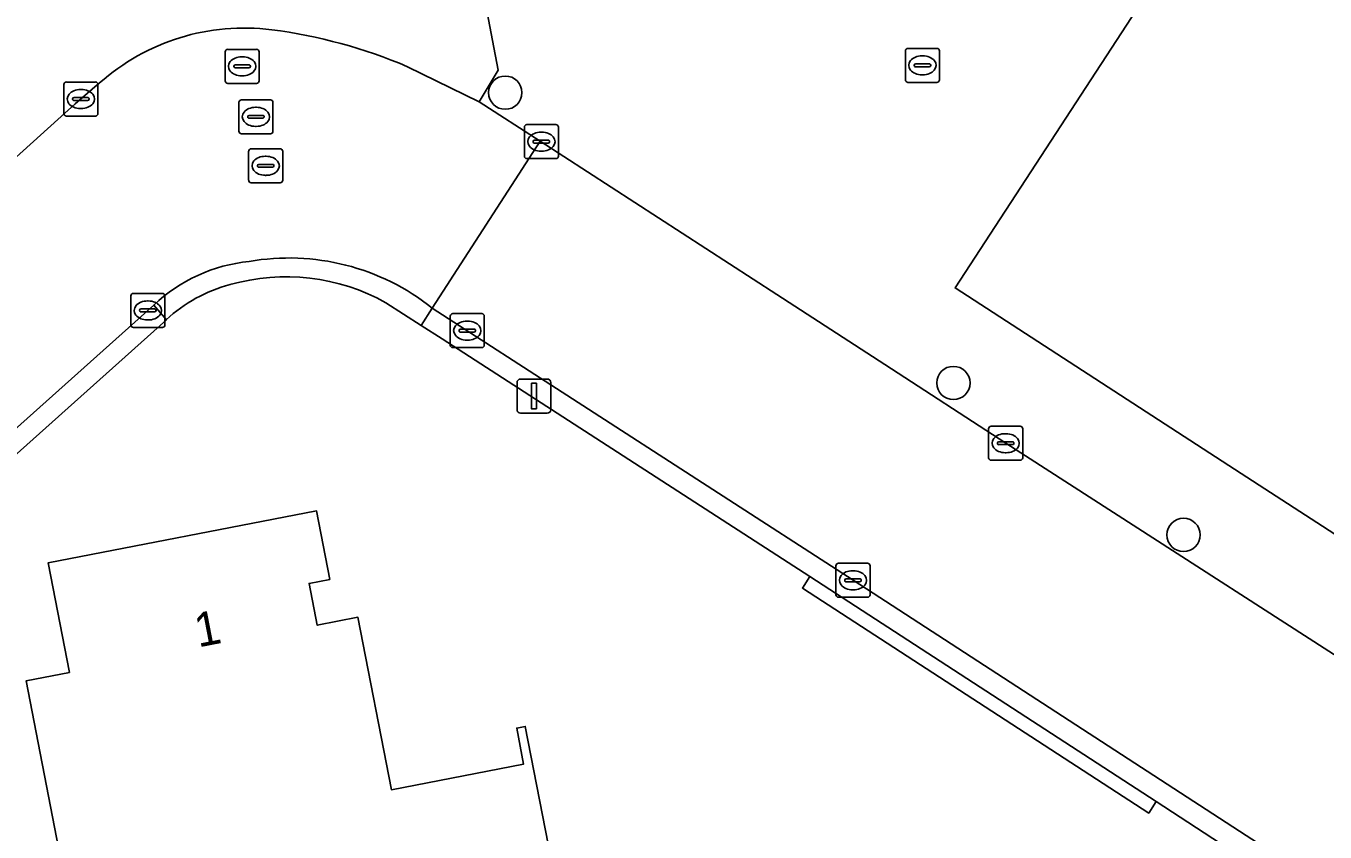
# Model space of a CAD drawing. Extents: x 157648 to 158502, y 379212 to 380938.
# Drawn here: x 158355.36 to 158393.55, y 380471.39 to 380495.07 of the extents above; entities that cross this region are included whole.
import ezdxf

# ---------------------------------------------------------------- set-up
doc = ezdxf.new("R2010")
doc.units = 0
for name, color, linetype in [('IMGEO_Boom', 7, 'Continuous'), ('IMGEO_Erf', 7, 'Continuous'), ('IMGEO_Groenvoorziening', 7, 'Continuous'), ('IMGEO_Haag', 7, 'Continuous'), ('IMGEO_Hek', 7, 'Continuous'), ('IMGEO_Kolk', 7, 'Continuous'), ('IMGEO_Lichtmast', 7, 'Continuous'), ('IMGEO_Pand', 7, 'Continuous'), ('IMGEO_Pand_nummerreeks', 7, 'Continuous'), ('IMGEO_Rijbaan_lokaal_open', 7, 'Continuous'), ('IMGEO_Rioolput', 7, 'Continuous'), ('IMGEO_Voetpad_open', 7, 'Continuous')]:
    doc.layers.add(name, color=color, linetype=linetype)

msp = doc.modelspace()

# ---------------------------------------------------------------- linework, layer by layer
at = {"layer": 'IMGEO_Boom'}
for centre in [(158369.454, 380493.113), (158382.628, 380484.583), (158389.393, 380480.119)]:
    msp.add_circle(centre, 0.489, dxfattribs=at)
at = {"layer": 'IMGEO_Erf'}
for points in [[(158380.582, 380515.062), (158381.881, 380508.316), (158377.849, 380507.539), (158377.739, 380508.108), (158374.457, 380507.476), (158370.48, 380506.71), (158371.129, 380503.345), (158363.628, 380501.901), (158364.015, 380500.041), (158364.616, 380497.15), (158368.462, 380497.886), (158387.396, 380501.51), (158388.452, 380496.229), (158382.675, 380487.376), (158391.091, 380481.923), (158399.153, 380476.703), (158402.85, 380476.983), (158408.306, 380485.065), (158411.427, 380489.696)], [(158393.178, 380468.812), (158392.666, 380469.161), (158390.971, 380470.261), (158391.189, 380470.597), (158388.589, 380472.285), (158388.371, 380471.949), (158378.189, 380478.557), (158378.407, 380478.893), (158367.597, 380485.882), (158366.984, 380486.274), (158365.946, 380486.942)], [(158359.49, 380486.443), (158322.721, 380453.552)]]:
    msp.add_lwpolyline(points, dxfattribs=at)
msp.add_lwpolyline([(158356.657, 380469.164), (158356.316, 380470.924), (158355.366, 380475.832), (158356.639, 380476.078), (158356.016, 380479.298), (158363.906, 380480.825), (158364.296, 380478.811), (158363.688, 380478.694), (158363.926, 380477.467), (158365.124, 380477.699), (158366.105, 380472.634), (158369.993, 380473.387), (158369.789, 380474.442), (158370.042, 380474.491), (158370.799, 380470.582), (158365.891, 380469.632), (158361.463, 380468.775), (158361.217, 380470.047)], close=True, dxfattribs=at)
for centre, radius, start, end in [((158363.014, 380481.675), 6.028, 60.8988, 105.9108), ((158362.461, 380483.255), 4.358, 104.6089, 132.9845)]:
    msp.add_arc(centre, radius, start, end, dxfattribs=at)
at = {"layer": 'IMGEO_Groenvoorziening'}
msp.add_lwpolyline([(158378.407, 380478.893), (158378.189, 380478.557), (158388.371, 380471.949), (158388.589, 380472.285)], close=True, dxfattribs=at)
at = {"layer": 'IMGEO_Haag'}
msp.add_lwpolyline([(158378.407, 380478.893), (158378.189, 380478.557), (158388.371, 380471.949), (158388.589, 380472.285)], close=True, dxfattribs=at)
at = {"layer": 'IMGEO_Hek'}
for points in [[(158391.091, 380481.923), (158382.675, 380487.376), (158388.452, 380496.229), (158387.396, 380501.51)], [(158378.407, 380478.893), (158367.597, 380485.882)], [(158388.589, 380472.285), (158391.189, 380470.597)]]:
    msp.add_lwpolyline(points, dxfattribs=at)
at = {"layer": 'IMGEO_Kolk'}
for p, q in [((158381.217, 380493.489), (158381.217, 380494.341)), ((158381.292, 380494.415), (158382.144, 380494.415)), ((158381.705, 380494.195), (158381.73, 380494.195)), ((158382.218, 380494.341), (158382.218, 380493.489)), ((158381.476, 380493.909), (158381.476, 380493.921)), ((158381.914, 380493.872), (158381.516, 380493.872)), ((158381.519, 380493.958), (158381.917, 380493.958)), ((158381.96, 380493.921), (158381.96, 380493.909)), ((158356.477, 380492.5), (158356.477, 380493.352)), ((158356.552, 380493.426), (158357.404, 380493.426)), ((158357.478, 380493.352), (158357.478, 380492.5)), ((158382.144, 380493.415), (158381.292, 380493.415)), ((158381.728, 380493.635), (158381.703, 380493.635)), ((158356.779, 380492.969), (158357.177, 380492.969)), ((158356.965, 380493.206), (158356.99, 380493.206)), ((158356.736, 380492.92), (158356.736, 380492.932)), ((158357.174, 380492.883), (158356.776, 380492.883)), ((158356.988, 380492.646), (158356.963, 380492.646)), ((158357.22, 380492.932), (158357.22, 380492.92)), ((158357.404, 380492.426), (158356.552, 380492.426)), ((158370.09, 380492.175), (158370.942, 380492.175)), ((158370.015, 380491.249), (158370.015, 380492.101)), ((158370.503, 380491.955), (158370.528, 380491.955)), ((158371.016, 380492.101), (158371.016, 380491.249)), ((158370.274, 380491.669), (158370.274, 380491.681)), ((158370.712, 380491.632), (158370.314, 380491.632)), ((158370.317, 380491.718), (158370.715, 380491.718)), ((158370.758, 380491.681), (158370.758, 380491.669)), ((158370.942, 380491.175), (158370.09, 380491.175)), ((158370.526, 380491.395), (158370.501, 380491.395)), ((158358.521, 380487.214), (158359.373, 380487.214)), ((158358.446, 380486.288), (158358.446, 380487.14)), ((158358.934, 380486.994), (158358.959, 380486.994)), ((158359.447, 380487.14), (158359.447, 380486.288)), ((158358.705, 380486.708), (158358.705, 380486.72)), ((158359.143, 380486.671), (158358.745, 380486.671)), ((158358.748, 380486.757), (158359.146, 380486.757)), ((158359.189, 380486.72), (158359.189, 380486.708)), ((158367.836, 380485.696), (158367.836, 380486.548)), ((158367.911, 380486.622), (158368.763, 380486.622)), ((158368.837, 380486.548), (158368.837, 380485.696)), ((158359.373, 380486.214), (158358.521, 380486.214)), ((158358.957, 380486.434), (158358.932, 380486.434)), ((158368.095, 380486.116), (158368.095, 380486.128)), ((158368.533, 380486.079), (158368.135, 380486.079)), ((158368.138, 380486.165), (158368.536, 380486.165)), ((158368.324, 380486.402), (158368.349, 380486.402)), ((158368.579, 380486.128), (158368.579, 380486.116)), ((158368.347, 380485.842), (158368.322, 380485.842)), ((158368.763, 380485.622), (158367.911, 380485.622)), ((158383.663, 380482.388), (158383.663, 380483.24)), ((158383.738, 380483.314), (158384.59, 380483.314)), ((158384.151, 380483.094), (158384.176, 380483.094)), ((158384.664, 380483.24), (158384.664, 380482.388)), ((158383.922, 380482.808), (158383.922, 380482.82)), ((158384.36, 380482.771), (158383.962, 380482.771)), ((158383.965, 380482.857), (158384.363, 380482.857)), ((158384.406, 380482.82), (158384.406, 380482.808)), ((158384.59, 380482.314), (158383.738, 380482.314)), ((158384.174, 380482.534), (158384.149, 380482.534)), ((158379.175, 380478.361), (158379.175, 380479.213)), ((158379.25, 380479.287), (158380.102, 380479.287)), ((158380.176, 380479.213), (158380.176, 380478.361)), ((158379.477, 380478.83), (158379.875, 380478.83)), ((158379.663, 380479.067), (158379.688, 380479.067)), ((158379.434, 380478.781), (158379.434, 380478.793)), ((158379.872, 380478.744), (158379.474, 380478.744)), ((158379.686, 380478.507), (158379.661, 380478.507)), ((158379.918, 380478.793), (158379.918, 380478.781)), ((158380.102, 380478.287), (158379.25, 380478.287))]:
    msp.add_line(p, q, dxfattribs=at)
for points in [[(158381.217, 380493.489), (158381.217, 380494.341)], [(158381.292, 380494.415), (158382.144, 380494.415)], [(158382.218, 380494.341), (158382.218, 380493.489)], [(158356.477, 380492.5), (158356.477, 380493.352)], [(158356.552, 380493.426), (158357.404, 380493.426)], [(158357.478, 380493.352), (158357.478, 380492.5)], [(158382.144, 380493.415), (158381.292, 380493.415)], [(158357.404, 380492.426), (158356.552, 380492.426)], [(158370.09, 380492.175), (158370.942, 380492.175)], [(158370.015, 380491.249), (158370.015, 380492.101)], [(158371.016, 380492.101), (158371.016, 380491.249)], [(158370.942, 380491.175), (158370.09, 380491.175)], [(158358.521, 380487.214), (158359.373, 380487.214)], [(158358.446, 380486.288), (158358.446, 380487.14)], [(158359.447, 380487.14), (158359.447, 380486.288)], [(158367.836, 380485.696), (158367.836, 380486.548)], [(158367.911, 380486.622), (158368.763, 380486.622)], [(158368.837, 380486.548), (158368.837, 380485.696)], [(158359.373, 380486.214), (158358.521, 380486.214)], [(158368.763, 380485.622), (158367.911, 380485.622)], [(158383.663, 380482.388), (158383.663, 380483.24)], [(158383.738, 380483.314), (158384.59, 380483.314)], [(158384.664, 380483.24), (158384.664, 380482.388)], [(158384.59, 380482.314), (158383.738, 380482.314)], [(158379.175, 380478.361), (158379.175, 380479.213)], [(158379.25, 380479.287), (158380.102, 380479.287)], [(158380.176, 380479.213), (158380.176, 380478.361)], [(158380.102, 380478.287), (158379.25, 380478.287)]]:
    msp.add_lwpolyline(points, dxfattribs=at)
for centre, radius, start, end in [((158381.294, 380494.339), 0.0765, 91.552, 178.448), ((158381.294, 380494.339), 0.0765, 91.552, 178.448), ((158382.142, 380494.339), 0.0765, 1.552, 88.448), ((158382.142, 380494.339), 0.0765, 1.552, 88.448), ((158381.516, 380493.918), 0.0403, 85.8775, 175.7526), ((158381.513, 380493.908), 0.0366, 178.938, 274.7102), ((158381.917, 380493.915), 0.043, 264.8664, 352.4533), ((158381.921, 380493.92), 0.0386, 1.7309, 96.639), ((158356.554, 380493.35), 0.0765, 91.552, 178.448), ((158356.554, 380493.35), 0.0765, 91.552, 178.448), ((158357.402, 380493.35), 0.0765, 1.552, 88.448), ((158357.402, 380493.35), 0.0765, 1.552, 88.448), ((158381.294, 380493.491), 0.0765, 181.552, 268.448), ((158381.294, 380493.491), 0.0765, 181.552, 268.448), ((158382.142, 380493.491), 0.0765, 271.552, 358.448), ((158382.142, 380493.491), 0.0765, 271.552, 358.448), ((158356.776, 380492.929), 0.0403, 85.8775, 175.7526), ((158357.181, 380492.931), 0.0386, 1.7309, 96.639), ((158356.773, 380492.919), 0.0366, 178.938, 274.7102), ((158357.177, 380492.926), 0.043, 264.8664, 352.4533), ((158356.554, 380492.502), 0.0765, 181.552, 268.448), ((158356.554, 380492.502), 0.0765, 181.552, 268.448), ((158357.402, 380492.502), 0.0765, 271.552, 358.448), ((158357.402, 380492.502), 0.0765, 271.552, 358.448), ((158370.092, 380492.099), 0.0765, 91.552, 178.448), ((158370.092, 380492.099), 0.0765, 91.552, 178.448), ((158370.94, 380492.099), 0.0765, 1.552, 88.448), ((158370.94, 380492.099), 0.0765, 1.552, 88.448), ((158370.314, 380491.678), 0.0403, 85.8775, 175.7526), ((158370.311, 380491.668), 0.0366, 178.938, 274.7102), ((158370.715, 380491.675), 0.043, 264.8664, 352.4533), ((158370.719, 380491.68), 0.0386, 1.7309, 96.639), ((158370.092, 380491.251), 0.0765, 181.552, 268.448), ((158370.092, 380491.251), 0.0765, 181.552, 268.448), ((158370.94, 380491.251), 0.0765, 271.552, 358.448), ((158370.94, 380491.251), 0.0765, 271.552, 358.448), ((158358.523, 380487.138), 0.0765, 91.552, 178.448), ((158358.523, 380487.138), 0.0765, 91.552, 178.448), ((158359.371, 380487.138), 0.0765, 1.552, 88.448), ((158359.371, 380487.138), 0.0765, 1.552, 88.448), ((158358.745, 380486.717), 0.0403, 85.8775, 175.7526), ((158358.742, 380486.707), 0.0366, 178.938, 274.7102), ((158359.146, 380486.714), 0.043, 264.8664, 352.4533), ((158359.15, 380486.719), 0.0386, 1.7309, 96.639), ((158367.913, 380486.546), 0.0765, 91.552, 178.448), ((158367.913, 380486.546), 0.0765, 91.552, 178.448), ((158368.761, 380486.546), 0.0765, 1.552, 88.448), ((158368.761, 380486.546), 0.0765, 1.552, 88.448), ((158358.523, 380486.29), 0.0765, 181.552, 268.448), ((158358.523, 380486.29), 0.0765, 181.552, 268.448), ((158359.371, 380486.29), 0.0765, 271.552, 358.448), ((158359.371, 380486.29), 0.0765, 271.552, 358.448), ((158368.135, 380486.125), 0.0403, 85.8775, 175.7526), ((158368.132, 380486.115), 0.0366, 178.938, 274.7102), ((158368.536, 380486.122), 0.043, 264.8664, 352.4533), ((158368.54, 380486.127), 0.0386, 1.7309, 96.639), ((158367.913, 380485.698), 0.0765, 181.552, 268.448), ((158367.913, 380485.698), 0.0765, 181.552, 268.448), ((158368.761, 380485.698), 0.0765, 271.552, 358.448), ((158368.761, 380485.698), 0.0765, 271.552, 358.448), ((158383.74, 380483.238), 0.0765, 91.552, 178.448), ((158383.74, 380483.238), 0.0765, 91.552, 178.448), ((158384.588, 380483.238), 0.0765, 1.552, 88.448), ((158384.588, 380483.238), 0.0765, 1.552, 88.448), ((158383.962, 380482.817), 0.0403, 85.8775, 175.7526), ((158383.959, 380482.807), 0.0366, 178.938, 274.7102), ((158384.363, 380482.814), 0.043, 264.8664, 352.4533), ((158384.367, 380482.819), 0.0386, 1.7309, 96.639), ((158383.74, 380482.39), 0.0765, 181.552, 268.448), ((158383.74, 380482.39), 0.0765, 181.552, 268.448), ((158384.588, 380482.39), 0.0765, 271.552, 358.448), ((158384.588, 380482.39), 0.0765, 271.552, 358.448), ((158379.252, 380479.211), 0.0765, 91.552, 178.448), ((158379.252, 380479.211), 0.0765, 91.552, 178.448), ((158380.1, 380479.211), 0.0765, 1.552, 88.448), ((158380.1, 380479.211), 0.0765, 1.552, 88.448), ((158379.474, 380478.79), 0.0403, 85.8775, 175.7526), ((158379.879, 380478.792), 0.0386, 1.7309, 96.639), ((158379.471, 380478.78), 0.0366, 178.938, 274.7102), ((158379.875, 380478.787), 0.043, 264.8664, 352.4533), ((158379.252, 380478.363), 0.0765, 181.552, 268.448), ((158379.252, 380478.363), 0.0765, 181.552, 268.448), ((158380.1, 380478.363), 0.0765, 271.552, 358.448), ((158380.1, 380478.363), 0.0765, 271.552, 358.448)]:
    msp.add_arc(centre, radius, start, end, dxfattribs=at)
for centre, major_axis, ratio, start_param, end_param in [((158381.704, 380493.915), (-0.387, 0.002), 0.722429, 4.712389, 7.853982), ((158381.729, 380493.915), (-0.39, 0.002), 0.717154, 1.570796, 4.712389), ((158356.964, 380492.926), (-0.387, 0.002), 0.722429, 4.712389, 7.853982), ((158356.989, 380492.926), (-0.39, 0.002), 0.717154, 1.570796, 4.712389), ((158370.502, 380491.675), (-0.387, 0.002), 0.722429, 4.712389, 7.853982), ((158370.527, 380491.675), (-0.39, 0.002), 0.717154, 1.570796, 4.712389), ((158358.933, 380486.714), (-0.387, 0.002), 0.722429, 4.712389, 7.853982), ((158358.958, 380486.714), (-0.39, 0.002), 0.717154, 1.570796, 4.712389), ((158368.323, 380486.122), (-0.387, 0.002), 0.722429, 4.712389, 7.853982), ((158368.348, 380486.122), (-0.39, 0.002), 0.717154, 1.570796, 4.712389), ((158384.15, 380482.814), (-0.387, 0.002), 0.722429, 4.712389, 7.853982), ((158384.175, 380482.814), (-0.39, 0.002), 0.717154, 1.570796, 4.712389), ((158379.662, 380478.787), (-0.387, 0.002), 0.722429, 4.712389, 7.853982), ((158379.687, 380478.787), (-0.39, 0.002), 0.717154, 1.570796, 4.712389)]:
    msp.add_ellipse(centre, major_axis=major_axis, ratio=ratio, start_param=start_param, end_param=end_param, dxfattribs=at)
at = {"layer": 'IMGEO_Lichtmast'}
for p, q in [((158369.8, 380483.799), (158369.8, 380484.599)), ((158369.8, 380484.599), (158369.8, 380483.799)), ((158369.9, 380484.699), (158370.69, 380484.699)), ((158370.69, 380484.699), (158369.9, 380484.699)), ((158370.79, 380484.599), (158370.79, 380483.799)), ((158370.79, 380483.799), (158370.79, 380484.599)), ((158370.69, 380483.699), (158369.9, 380483.699)), ((158369.9, 380483.699), (158370.69, 380483.699))]:
    msp.add_line(p, q, dxfattribs=at)
msp.add_lwpolyline([(158370.22, 380484.574), (158370.37, 380484.574), (158370.37, 380483.824), (158370.22, 380483.824), (158370.22, 380484.574)], dxfattribs=at)
for centre, start, end in [((158369.9, 380484.599), 90, 180), ((158369.9, 380484.599), 90, 180), ((158370.69, 380484.599), 0, 90), ((158370.69, 380484.599), 360, 90), ((158369.9, 380483.799), 180, 270), ((158369.9, 380483.799), 180, 270), ((158370.69, 380483.799), 270, 0), ((158370.69, 380483.799), 270, 0)]:
    msp.add_arc(centre, 0.1, start, end, dxfattribs=at)
at = {"layer": 'IMGEO_Pand'}
msp.add_lwpolyline([(158364.296, 380478.811), (158363.906, 380480.825), (158356.016, 380479.298), (158356.639, 380476.078), (158355.366, 380475.832), (158356.316, 380470.924), (158356.657, 380469.164), (158361.217, 380470.047), (158361.463, 380468.775), (158365.891, 380469.632), (158370.799, 380470.582), (158370.042, 380474.491), (158369.789, 380474.442), (158369.993, 380473.387), (158366.105, 380472.634), (158365.124, 380477.699), (158363.926, 380477.467), (158363.688, 380478.694)], close=True, dxfattribs=at)
at = {"layer": 'IMGEO_Rijbaan_lokaal_open'}
for points in [[(158367.307, 380486.782), (158370.478, 380491.685), (158368.685, 380492.845), (158366.583, 380493.876)], [(158357.527, 380493.399), (158356.81, 380492.78), (158353.442, 380489.751), (158344.47, 380481.713), (158341.103, 380478.688), (158332.553, 380471.005), (158329.173, 380467.979), (158318.397, 380458.269), (158315.491, 380455.507), (158311.559, 380450.954)], [(158370.478, 380491.685), (158367.307, 380486.782), (158379.676, 380478.787), (158393.724, 380469.669)], [(158397.402, 380474.299), (158384.164, 380482.814), (158380.607, 380485.124), (158377.439, 380487.183), (158370.478, 380491.685)], [(158335.204, 380465.495), (158338.581, 380468.517), (158347.153, 380476.187), (158350.545, 380479.214), (158359.122, 380486.871)]]:
    msp.add_lwpolyline(points, dxfattribs=at)
for centre, radius, start, end in [((158361.782, 380488.595), 6.417, 82.796, 131.5351), ((158360.605, 380479.776), 15.315, 67.026, 82.5657), ((158362.394, 380483.424), 4.753, 95.7106, 133.5069), ((158363.095, 380481.501), 6.755, 51.4257, 100.0118)]:
    msp.add_arc(centre, radius, start, end, dxfattribs=at)
at = {"layer": 'IMGEO_Rioolput'}
for p, q in [((158361.218, 380493.46), (158361.218, 380494.312)), ((158361.293, 380494.386), (158362.145, 380494.386)), ((158361.706, 380494.166), (158361.731, 380494.166)), ((158362.219, 380494.312), (158362.219, 380493.46)), ((158361.477, 380493.88), (158361.477, 380493.892)), ((158361.915, 380493.843), (158361.517, 380493.843)), ((158361.52, 380493.929), (158361.918, 380493.929)), ((158361.961, 380493.892), (158361.961, 380493.88)), ((158362.145, 380493.386), (158361.293, 380493.386)), ((158361.729, 380493.606), (158361.704, 380493.606)), ((158361.623, 380491.977), (158361.623, 380492.829)), ((158361.698, 380492.903), (158362.55, 380492.903)), ((158362.111, 380492.683), (158362.136, 380492.683)), ((158362.624, 380492.829), (158362.624, 380491.977)), ((158361.882, 380492.397), (158361.882, 380492.409)), ((158362.32, 380492.36), (158361.922, 380492.36)), ((158361.925, 380492.446), (158362.323, 380492.446)), ((158362.366, 380492.409), (158362.366, 380492.397)), ((158362.55, 380491.903), (158361.698, 380491.903)), ((158362.134, 380492.123), (158362.109, 380492.123)), ((158361.985, 380491.464), (158362.837, 380491.464)), ((158361.91, 380490.538), (158361.91, 380491.39)), ((158362.398, 380491.244), (158362.423, 380491.244)), ((158362.911, 380491.39), (158362.911, 380490.538)), ((158362.169, 380490.958), (158362.169, 380490.97)), ((158362.607, 380490.921), (158362.209, 380490.921)), ((158362.212, 380491.007), (158362.61, 380491.007)), ((158362.421, 380490.684), (158362.396, 380490.684)), ((158362.653, 380490.97), (158362.653, 380490.958)), ((158362.837, 380490.464), (158361.985, 380490.464))]:
    msp.add_line(p, q, dxfattribs=at)
for points in [[(158361.218, 380493.46), (158361.218, 380494.312)], [(158361.293, 380494.386), (158362.145, 380494.386)], [(158362.219, 380494.312), (158362.219, 380493.46)], [(158362.145, 380493.386), (158361.293, 380493.386)], [(158361.623, 380491.977), (158361.623, 380492.829)], [(158361.698, 380492.903), (158362.55, 380492.903)], [(158362.624, 380492.829), (158362.624, 380491.977)], [(158362.55, 380491.903), (158361.698, 380491.903)], [(158361.985, 380491.464), (158362.837, 380491.464)], [(158361.91, 380490.538), (158361.91, 380491.39)], [(158362.911, 380491.39), (158362.911, 380490.538)], [(158362.837, 380490.464), (158361.985, 380490.464)]]:
    msp.add_lwpolyline(points, dxfattribs=at)
for centre, radius, start, end in [((158361.295, 380494.31), 0.0765, 91.552, 178.448), ((158361.295, 380494.31), 0.0765, 91.552, 178.448), ((158362.143, 380494.31), 0.0765, 1.552, 88.448), ((158362.143, 380494.31), 0.0765, 1.552, 88.448), ((158361.517, 380493.889), 0.0403, 85.8775, 175.7526), ((158361.514, 380493.879), 0.0366, 178.938, 274.7102), ((158361.918, 380493.886), 0.043, 264.8664, 352.4533), ((158361.922, 380493.891), 0.0386, 1.7309, 96.639), ((158361.295, 380493.462), 0.0765, 181.552, 268.448), ((158361.295, 380493.462), 0.0765, 181.552, 268.448), ((158362.143, 380493.462), 0.0765, 271.552, 358.448), ((158362.143, 380493.462), 0.0765, 271.552, 358.448), ((158361.7, 380492.827), 0.0765, 91.552, 178.448), ((158361.7, 380492.827), 0.0765, 91.552, 178.448), ((158362.548, 380492.827), 0.0765, 1.552, 88.448), ((158362.548, 380492.827), 0.0765, 1.552, 88.448), ((158361.922, 380492.406), 0.0403, 85.8775, 175.7526), ((158361.919, 380492.396), 0.0366, 178.938, 274.7102), ((158362.323, 380492.403), 0.043, 264.8664, 352.4533), ((158362.327, 380492.408), 0.0386, 1.7309, 96.639), ((158361.7, 380491.979), 0.0765, 181.552, 268.448), ((158361.7, 380491.979), 0.0765, 181.552, 268.448), ((158362.548, 380491.979), 0.0765, 271.552, 358.448), ((158362.548, 380491.979), 0.0765, 271.552, 358.448), ((158361.987, 380491.388), 0.0765, 91.552, 178.448), ((158361.987, 380491.388), 0.0765, 91.552, 178.448), ((158362.835, 380491.388), 0.0765, 1.552, 88.448), ((158362.835, 380491.388), 0.0765, 1.552, 88.448), ((158362.209, 380490.967), 0.0403, 85.8775, 175.7526), ((158362.206, 380490.957), 0.0366, 178.938, 274.7102), ((158362.61, 380490.964), 0.043, 264.8664, 352.4533), ((158362.614, 380490.969), 0.0386, 1.7309, 96.639), ((158361.987, 380490.54), 0.0765, 181.552, 268.448), ((158361.987, 380490.54), 0.0765, 181.552, 268.448), ((158362.835, 380490.54), 0.0765, 271.552, 358.448), ((158362.835, 380490.54), 0.0765, 271.552, 358.448)]:
    msp.add_arc(centre, radius, start, end, dxfattribs=at)
for centre, major_axis, ratio, start_param, end_param in [((158361.705, 380493.886), (-0.387, 0.002), 0.722429, 4.712389, 7.853982), ((158361.73, 380493.886), (-0.39, 0.002), 0.717154, 1.570796, 4.712389), ((158362.11, 380492.403), (-0.387, 0.002), 0.722429, 4.712389, 7.853982), ((158362.135, 380492.403), (-0.39, 0.002), 0.717154, 1.570796, 4.712389), ((158362.397, 380490.964), (-0.387, 0.002), 0.722429, 4.712389, 7.853982), ((158362.422, 380490.964), (-0.39, 0.002), 0.717154, 1.570796, 4.712389)]:
    msp.add_ellipse(centre, major_axis=major_axis, ratio=ratio, start_param=start_param, end_param=end_param, dxfattribs=at)
at = {"layer": 'IMGEO_Voetpad_open'}
for points in [[(158388.452, 380496.229), (158387.396, 380501.51), (158368.462, 380497.886), (158369.249, 380493.776), (158368.685, 380492.845), (158370.478, 380491.685), (158377.439, 380487.183), (158380.607, 380485.124), (158384.164, 380482.814), (158397.402, 380474.299)], [(158366.583, 380493.876), (158368.685, 380492.845), (158369.249, 380493.776), (158368.462, 380497.886)], [(158399.794, 380473.335), (158402.85, 380476.983), (158399.153, 380476.703), (158391.091, 380481.923), (158382.675, 380487.376), (158388.452, 380496.229)], [(158309.213, 380452.852), (158311.559, 380450.954), (158315.491, 380455.507), (158318.397, 380458.269), (158329.173, 380467.979), (158332.553, 380471.005), (158341.103, 380478.688), (158344.47, 380481.713), (158353.442, 380489.751), (158356.81, 380492.78), (158357.527, 380493.399)], [(158322.721, 380453.552), (158359.49, 380486.443), (158359.122, 380486.871), (158350.545, 380479.214), (158347.153, 380476.187), (158338.581, 380468.517), (158335.204, 380465.495), (158326.203, 380457.468), (158322.828, 380454.46), (158322.086, 380453.781)], [(158359.122, 380486.871), (158359.49, 380486.443)], [(158365.946, 380486.942), (158366.984, 380486.274), (158367.307, 380486.782)], [(158379.676, 380478.787), (158367.307, 380486.782), (158366.984, 380486.274), (158367.597, 380485.882), (158378.407, 380478.893), (158388.589, 380472.285), (158391.189, 380470.597), (158392.888, 380469.494), (158393.39, 380469.152)], [(158393.724, 380469.669), (158379.676, 380478.787)]]:
    msp.add_lwpolyline(points, dxfattribs=at)
for centre, radius, start, end in [((158361.782, 380488.595), 6.417, 82.796, 131.5351), ((158360.605, 380479.776), 15.315, 67.026, 82.5657), ((158362.394, 380483.424), 4.753, 95.7106, 133.5069), ((158363.095, 380481.501), 6.755, 51.4257, 100.0118), ((158363.014, 380481.675), 6.028, 60.8988, 105.9108), ((158362.461, 380483.255), 4.358, 104.6089, 132.9845)]:
    msp.add_arc(centre, radius, start, end, dxfattribs=at)

# ---------------------------------------------------------------- texts
at = {"layer": 'IMGEO_Pand_nummerreeks'}
msp.add_text('1', height=1, rotation=10.9534, dxfattribs=at).set_placement((158360.426, 380476.811))

doc.saveas('drawing.dxf')
